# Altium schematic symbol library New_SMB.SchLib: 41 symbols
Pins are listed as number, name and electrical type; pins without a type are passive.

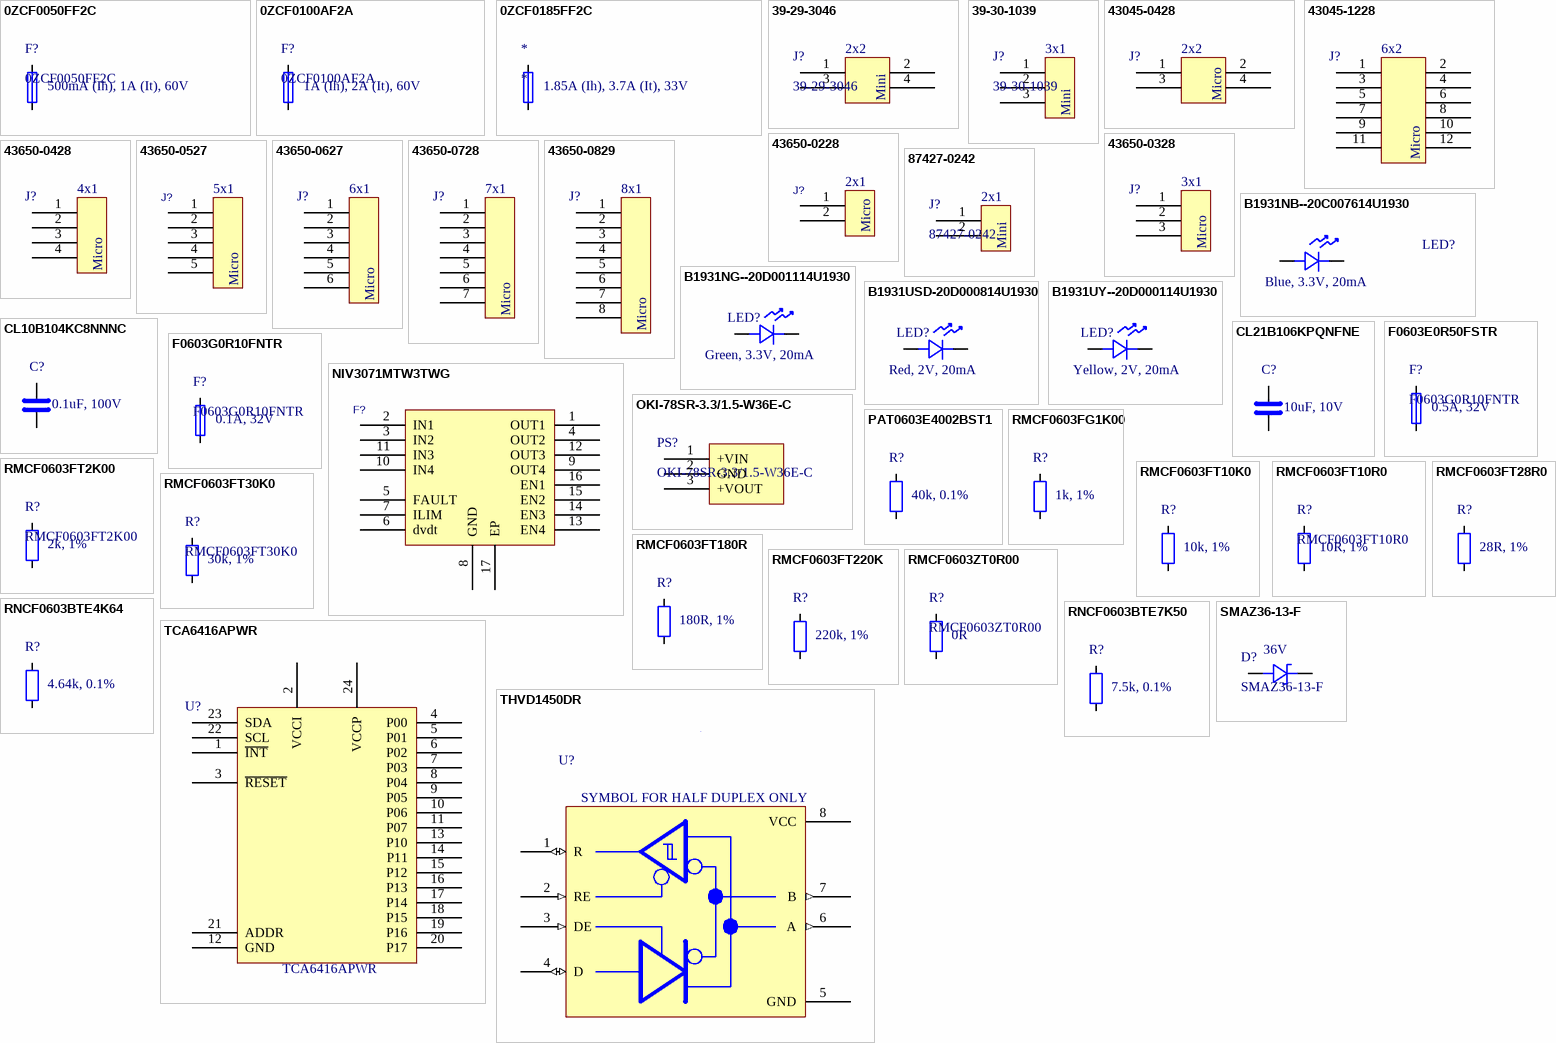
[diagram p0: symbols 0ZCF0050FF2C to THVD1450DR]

## 0ZCF0050FF2C
designator F?  Parameter 1: 500mA (Ih), 1A (It), 60V
PTC Resettable Fuse, 60V, 0.3ohm, Surface Mount; Manufacturer: Bel; Power: 1.5W; Thermistor Application: TEMPERATURE SENSING
footprint 0ZCF
pins: 1, 2

## 0ZCF0100AF2A
designator F?  Parameter 1: 1A (Ih), 2A (It), 60V
PTC Resettable Fuse, 60V, 0.09ohm, Surface Mount; Manufacturer: Bel; Thermistor Application: TEMPERATURE SENSING
footprint 0ZCF
pins: 1, 2

## 0ZCF0185FF2C
designator *  Parameter 1: 1.85A (Ih), 3.7A (It), 33V
PTC Resettable Fuse, 33V, 0.04ohm, Surface Mount; Manufacturer: Bel; Manufacturer Part Number: 0ZCF0185FF2C; Power: 1.5W; Thermistor Application: TEMPERATURE SENSING
footprint 0ZCF
pins: 1, 2

## 39-29-3046
designator J?  Parameter 1: 2x2  Parameter 2: Mini
Rectangular Power Connector, 4 Contact(s), Male, Solder Terminal, Plug; Manufacturer: Molex; Connector Type: Power,Rectangular; Option: General Purpose; Contact Resistance: 10mR; Contact Style: SQ PIN-SKT; Dielectric Withstanding Voltage (AC): 1.5kV; Durability: 30Cycles; Empty Shell: No; Insertion Force-Max: 6.672N; Insulation Resistance: 1GR; Mating Information: MULTIPLE MATING PARTS AVAILABLE; Number Of Connectors: 1; Number Of PCB Rows: 2; Polarization Key: POLARIZED HOUSING; Rated Current (Signal): 8A; Number of Contacts: 4; Withdrawl Force-Min: 3.1136N; Body Breadth: 0.378inch; Body Depth: 0.504inch; Body Length: 0.38inch; Mating Contact Pitch: 0.165inch; Mounting Option 1: POLARIZED LCK; Mounting Option 2: LOCKING; PCB Contact Row Spacing: 5.5118mm; Plating Thickness: 35uin; Reference Standard: UL; Reliability: COMMERCIAL
footprint 39-29-3046
pins: 1, 2, 3, 4

## 39-30-1039
designator J?  Parameter 1: 3x1  Parameter 2: Mini
Rectangular Power Connector, 3 Contact(s), Male, Solder Terminal, Plug; Manufacturer: Molex; Manufacturer Series: 5566; Connector Type: Power,Rectangular; Option: General Purpose; Board Mounting Option: COMPLIANT BOARDLOCK; Contact Resistance: 10mR; Contact Style: SQ PIN-SKT; Dielectric Withstanding Voltage (AC): 1.5kV; Durability: 30Cycles; Empty Shell: No; Insulation Resistance: 1GR; Mating Information: MULTIPLE MATING PARTS AVAILABLE; Rated Current (Signal): 9A; Number of Contacts: 3; Insertion Force-Max: 6.672N; Number Of Connectors: 1; Polarization Key: HOUSING SIDE; Withdrawl Force-Min: 3.1136N; Body Breadth: 0.213inch; Body Depth: 0.504inch; Body Length: 0.543inch; Mounting Option 1: POLARIZED LCK; Mounting Option 2: LOCKING; Plating Thickness: 35uin; Mating Contact Pitch: 0.165inch; Reference Standard: UL; Reliability: COMMERCIAL
footprint 39-30-1039
pins: 1, 2, 3

## 43045-0428
designator J?  Parameter 1: 2x2  Parameter 2: Micro  (hidden comment: 43045-0428)
Board Connector, 4 Contact(s), 2 Row(s), Male, Straight, Solder Terminal, Locking, Black Insulator, Receptacle; Manufacturer: Molex; Throw Configuration: S0P4; Option: General Purpose; Board Mounting Option: PEG; Contact Resistance: 10mR; Contact Style: SQ PIN-SKT; Filter Feature: No; Insertion Force-Max: 8.0064N; Insulation Resistance: 1GR; Mating Information: MULTIPLE MATING PARTS AVAILABLE; Rated Current (Signal): 2.5A; Withdrawl Force-Min: 3.5584N; Body Breadth: 0.29inch; Body Depth: 0.39inch; Body Length: 0.38inch; Plating Thickness: 15uin; Reference Standard: UL; Reliability: COMMERCIAL; Number Of Connectors: 1; Number of Rows Loaded: 2; Number of Contacts: 4
footprint 43045-0428
pins: 1, 2, 3, 4

## 43045-1228
designator J?  Parameter 1: 6x2  Parameter 2: Micro  (hidden comment: 43045-1228)
Board Connector, 12 Contact(s), 2 Row(s), Male, Straight, Solder Terminal, Locking, Black Insulator, Receptacle; Manufacturer: Molex; Throw Configuration: S0P12; Option: General Purpose; Board Mounting Option: PEG; Contact Resistance: 10mR; Contact Style: SQ PIN-SKT; Filter Feature: No; Insertion Force-Max: 8.0064N; Insulation Resistance: 1GR; Mating Information: MULTIPLE MATING PARTS AVAILABLE; Number Of Connectors: 1; Number of Rows Loaded: 2; Rated Current (Signal): 2.5A; Number of Contacts: 12; Withdrawl Force-Min: 3.5584N; Body Breadth: 0.29inch; Body Depth: 0.39inch; Body Length: 0.852inch; Plating Thickness: 15uin; Reference Standard: UL; Reliability: COMMERCIAL
footprint 43045-1228
pins: 1, 2, 3, 4, 5, 6, 7, 8, 9, 10, 11, 12

## 43650-0228
designator J?  Parameter 1: 2x1  Parameter 2: Micro  (hidden comment: 43650-0228)
Rectangular Power Connector, 2 Contact(s), Female, Solder Terminal; Manufacturer: Molex; Manufacturer Series: 43650; Connector Type: Power,Rectangular; Option: General Purpose; Board Mounting Option: PEG; Body/Shell Style: RECEPTACLE; Contact Resistance: 10mR; Contact Style: SQ PIN-SKT; Dielectric Withstanding Voltage (AC): 1.5kV; Durability: 30Cycles; Empty Shell: No; Insertion Force-Max: 8.0064N; Insulation Resistance: 1GR; Mating Information: MULTIPLE MATING PARTS AVAILABLE; Number Of Connectors: 1; Polarization Key: POLARIZED HOUSING; Rated Current (Signal): 5A; Number of Contacts: 2; Withdrawl Force-Min: 3.614N; Body Breadth: 0.219inch; Body Depth: 0.39inch; Body Length: 0.38inch; Mating Contact Pitch: 0.118inch; Mounting Option 1: POLARIZED LCK; Mounting Option 2: LOCKING; Plating Thickness: 15uin; Reference Standard: UL; Reliability: COMMERCIAL
footprint 0436500228
footprint 43650-0228
pins: 1, 2

## 43650-0328
designator J?  Parameter 1: 3x1  Parameter 2: Micro  (hidden comment: 43650-0328)
Rectangular Power Connector, 3 Contact(s), Female, Solder Terminal; Manufacturer: Molex; Manufacturer Series: 43650; Connector Type: Power,Rectangular; Option: General Purpose; Board Mounting Option: PEG; Body/Shell Style: RECEPTACLE; Contact Resistance: 10mR; Contact Style: SQ PIN-SKT; Dielectric Withstanding Voltage (AC): 1.5kV; Durability: 30Cycles; Empty Shell: No; Insertion Force-Max: 8.0064N; Insulation Resistance: 1GR; Mating Information: MULTIPLE MATING PARTS AVAILABLE; Number Of Connectors: 1; Polarization Key: POLARIZED HOUSING; Rated Current (Signal): 5A; Number of Contacts: 3; Withdrawl Force-Min: 3.614N; Body Breadth: 0.219inch; Body Depth: 0.39inch; Body Length: 0.498inch; Mating Contact Pitch: 0.118inch; Mounting Option 1: POLARIZED LCK; Mounting Option 2: LOCKING; Plating Thickness: 15uin; Reference Standard: UL; Reliability: COMMERCIAL
footprint 43650-0328
pins: 1, 2, 3

## 43650-0428
designator J?  Parameter 1: 4x1  Parameter 2: Micro  (hidden comment: 43650-0428)
Rectangular Power Connector, 4 Contact(s), Female, Solder Terminal; Manufacturer: Molex; Manufacturer Series: 43650; Connector Type: Power,Rectangular; Option: General Purpose; Board Mounting Option: PEG; Body/Shell Style: RECEPTACLE; Contact Resistance: 10mR; Contact Style: SQ PIN-SKT; Dielectric Withstanding Voltage (AC): 1.5kV; Durability: 30Cycles; Empty Shell: No; Insertion Force-Max: 8.0064N; Insulation Resistance: 1GR; Mating Information: MULTIPLE MATING PARTS AVAILABLE; Number Of Connectors: 1; Polarization Key: POLARIZED HOUSING; Rated Current (Signal): 5A; Number of Contacts: 4; Withdrawl Force-Min: 3.614N; Body Breadth: 0.219inch; Body Depth: 0.39inch; Body Length: 0.616inch; Mating Contact Pitch: 0.118inch; Mounting Option 1: POLARIZED LCK; Mounting Option 2: LOCKING; Plating Thickness: 15uin; Reference Standard: UL; Reliability: COMMERCIAL
footprint 43650-0428
pins: 1, 2, 3, 4

## 43650-0527
designator J?  Parameter 1: 5x1  Parameter 2: Micro  (hidden comment: 43650-0527)
Rectangular Power Connector, 5 Contact(s), Female, Solder Terminal; Manufacturer: Molex; Connector Type: Power,Rectangular; Option: General Purpose; Board Mounting Option: PEG; Body/Shell Style: RECEPTACLE; Contact Resistance: 10mR; Contact Style: SQ PIN-SKT; Dielectric Withstanding Voltage (AC): 1.5kV; Durability: 30Cycles; Empty Shell: No; Insertion Force-Max: 8.0064N; Insulation Resistance: 1GR; Mating Information: MULTIPLE MATING PARTS AVAILABLE; Number Of Connectors: 1; Polarization Key: POLARIZED HOUSING; Rated Current (Signal): 5A; Number of Contacts: 5; Withdrawl Force-Min: 3.614N; Body Breadth: 0.219inch; Body Depth: 0.39inch; Body Length: 0.734inch; Mating Contact Pitch: 0.118inch; Mounting Option 1: POLARIZED LCK; Mounting Option 2: LOCKING; Plating Thickness: 100uin; Reference Standard: UL; Reliability: COMMERCIAL
footprint 0436500527
footprint 43650-0527
pins: 1, 2, 3, 4, 5

## 43650-0627
designator J?  Parameter 1: 6x1  Parameter 2: Micro  (hidden comment: 43650-0627)
Rectangular Power Connector, 6 Contact(s), Female, Solder Terminal; Manufacturer: Molex; Manufacturer Series: 43650; Connector Type: Power,Rectangular; Option: General Purpose; Board Mounting Option: PEG; Body/Shell Style: RECEPTACLE; Contact Resistance: 10mR; Contact Style: SQ PIN-SKT; Dielectric Withstanding Voltage (AC): 1.5kV; Durability: 30Cycles; Empty Shell: No; Insertion Force-Max: 8.0064N; Insulation Resistance: 1GR; Mating Information: MULTIPLE MATING PARTS AVAILABLE; Number Of Connectors: 1; Polarization Key: POLARIZED HOUSING; Rated Current (Signal): 5A; Number of Contacts: 6; Withdrawl Force-Min: 3.614N; Body Breadth: 0.219inch; Body Depth: 0.39inch; Body Length: 0.852inch; Mating Contact Pitch: 0.118inch; Mounting Option 1: POLARIZED LCK; Mounting Option 2: LOCKING; Plating Thickness: 100uin; Reference Standard: UL; Reliability: COMMERCIAL
footprint 43650-0627
pins: 1, 2, 3, 4, 5, 6

## 43650-0728
designator J?  Parameter 1: 7x1  Parameter 2: Micro  (hidden comment: 43650-0728)
Rectangular Power Connector, 7 Contact(s), Female, Solder Terminal; Manufacturer: Molex; Manufacturer Series: 43650; Connector Type: Power,Rectangular; Option: General Purpose; Board Mounting Option: PEG; Body/Shell Style: RECEPTACLE; Contact Resistance: 10mR; Contact Style: SQ PIN-SKT; Dielectric Withstanding Voltage (AC): 1.5kV; Durability: 30Cycles; Empty Shell: No; Insertion Force-Max: 8.0064N; Insulation Resistance: 1GR; Mating Information: MULTIPLE MATING PARTS AVAILABLE; Number Of Connectors: 1; Polarization Key: POLARIZED HOUSING; Rated Current (Signal): 5A; Number of Contacts: 7; Withdrawl Force-Min: 3.614N; Body Breadth: 0.219inch; Body Depth: 0.39inch; Body Length: 0.97inch; Mating Contact Pitch: 0.118inch; Mounting Option 1: POLARIZED LCK; Mounting Option 2: LOCKING; Plating Thickness: 15uin; Reference Standard: UL; Reliability: COMMERCIAL
footprint 43650-0728
pins: 1, 2, 3, 4, 5, 6, 7

## 43650-0829
designator J?  Parameter 1: 8x1  Parameter 2: Micro  (hidden comment: 43650-0829)
Rectangular Power Connector, 8 Contact(s), Female, Solder Terminal; Manufacturer: Molex; Manufacturer Series: 43650; Connector Type: Power,Rectangular; Option: General Purpose; Board Mounting Option: PEG; Body/Shell Style: RECEPTACLE; Contact Resistance: 10mR; Contact Style: SQ PIN-SKT; Dielectric Withstanding Voltage (AC): 1.5kV; Durability: 30Cycles; Empty Shell: No; Insertion Force-Max: 8.0064N; Insulation Resistance: 1GR; Mating Information: MULTIPLE MATING PARTS AVAILABLE; Number Of Connectors: 1; Polarization Key: POLARIZED HOUSING; Rated Current (Signal): 5A; Number of Contacts: 8; Withdrawl Force-Min: 3.614N; Body Breadth: 0.219inch; Body Depth: 0.39inch; Body Length: 1.089inch; Mating Contact Pitch: 0.118inch; Mounting Option 1: POLARIZED LCK; Mounting Option 2: LOCKING; Plating Thickness: 30uin; Reference Standard: UL; Reliability: COMMERCIAL
footprint 43650-0829
pins: 1, 2, 3, 4, 5, 6, 7, 8

## 87427-0242
designator J?  Parameter 1: 2x1  Parameter 2: Mini
Rectangular Power Connector, 2 Contact(s), Male, Solder Terminal, Receptacle; Manufacturer: Molex; Connector Type: Power,Rectangular; Option: General Purpose; Contact Resistance: 10mR; Contact Style: SQ PIN-SKT; Dielectric Withstanding Voltage (AC): 1.5kV; Durability: 30Cycles; Empty Shell: No; Insertion Force-Max: 6.672N; Insulation Resistance: 1GR; Mating Information: MULTIPLE MATING PARTS AVAILABLE; Number Of Connectors: 1; Number Of PCB Rows: 2; Polarization Key: POLARIZED HOUSING; Rated Current (Signal): 9A; Withdrawl Force-Min: 3.0024N; Body Breadth: 0.449inch; Body Depth: 0.531inch; Body Length: 0.213inch; Mating Contact Pitch: 0.165inch; Mounting Option 1: POLARIZED LCK; Mounting Option 2: LOCKING; PCB Contact Row Spacing: 4.191mm; Plating Thickness: 100uin; Reference Standard: UL; Reliability: COMMERCIAL
footprint 87427-0242
pins: 1, 2

## B1931NB--20C007614U1930
designator LED?  Parameter 1: Blue, 3.3V, 20mA  (hidden comment: B1931NB--20C007614U1930)
Led Blue Clear 1608 SMD; Manufacturer: Inolux
footprint LED_0603
pins: 1, 2

## B1931NG--20D001114U1930
designator LED?  Parameter 1: Green, 3.3V, 20mA  (hidden comment: B1931NG--20D001114U1930)
Led Green Diffused 0603 SMD; Manufacturer: Inolux
footprint LED_0603
pins: 1, 2

## B1931USD-20D000814U1930
designator LED?  Parameter 1: Red, 2V, 20mA  (hidden comment: B1931USD-20D000814U1930)
Led Red Diffused 0603 SMD; Manufacturer: Inolux
footprint LED_0603
pins: 1, 2

## B1931UY--20D000114U1930
designator LED?  Parameter 1: Yellow, 2V, 20mA  (hidden comment: B1931UY--20D000114U1930)
Led Yellow Clear 1608 SMD; Manufacturer: Inolux
footprint LED_0603
pins: 1, 2

## CL10B104KC8NNNC
designator C?  Parameter 1: 0.1uF, 100V  (hidden comment: CL10B104KC8NNNC)
Ceramic Capacitor, Multilayer, Ceramic, 100V, 10% +Tol, 10% -Tol, X7R, 15% TC, 0.1uF, Surface Mount, 0603; Manufacturer: Samsung; Multilayer: Yes; Value: 100nF
footprint C_0603
pins: 1, 2

## CL21B106KPQNFNE
designator C?  Parameter 1: 10uF, 10V  (hidden comment: CL21B106KPQNFNE)
Ceramic Capacitor, Multilayer, Ceramic, 10V, 10% +Tol, 10% -Tol, X7R, 15% TC, 10uF, Surface Mount, 0805; Manufacturer: Samsung; Multilayer: Yes
footprint C_0805
pins: 1, 2

## F0603E0R50FSTR
designator F?, comment F0603G0R10FNTR  Parameter 1: 0.5A, 32V
Electric Fuse, Fast Blow, 0.5A, 32VAC, 32VDC, 50A (IR), Surface Mount, 0603; Manufacturer: Kyocera AVX; Manufacturer Part Number: F0603E0R50FSTR; Manufacturer Series: F0603E; Joule-integral-Nom: 0.0003J; Current Rating: 500mA; Voltage Rating (AC): 32V
footprint FUSE_0603
pins: 1, 2

## F0603G0R10FNTR
designator F?  Parameter 1: 0.1A, 32V
Electric Fuse, Fast Blow, 0.1A, 32VAC, 32VDC, Surface Mount; Manufacturer: Kyocera AVX; Joule-integral-Nom: 7E-06J; Current Rating: 100mA; Body Breadth: 0.81mm; Body Height: 0.61mm; Body Length or Diameter: 1.6mm; Reference Standard: UL
footprint FUSE_0603
pins: 1, 2

## NIV3071MTW3TWG
designator F?  (value not drawn)
Electronic fuse (eFuse) 4-channel, 8V to 60V, 10A in 5x6mm package Latch version; Manufacturer: onsemi
footprint 16-WQFN-5x6
pins: 1 OUT1, 2 IN1, 3 IN2, 4 OUT2, 5 FAULT, 6 dvdt, 7 ILIM, 8 GND, 9 OUT4, 10 IN4, 11 IN3, 12 OUT3, 13 EN4, 14 EN3, 15 EN2, 16 EN1, 17 EP

## OKI-78SR-3.3/1.5-W36E-C
designator PS?
DC-DC Regulated Power Supply Module, 1 Output, 5.15W, Hybrid; Manufacturer: Murata; Max Supply Voltage: 36V; Min Input Voltage: 7V; Nominal Supply Voltage: 12V; Load Regulation-Max: 0.4%; Channels: 1; Max Output Voltage: 3.432V; Min Output Voltage: 3.168V; Nominal Output Voltage: 3.3V; Surface Mount: No; Trim/Adjustable Output: No
footprint OKI-78SR-5&slash_1.5-W36E-C
pins: 1 +VIN (power), 2 GND (power), 3 +VOUT (power)

## PAT0603E4002BST1
designator R?  Parameter 1: 40k, 0.1%  (hidden comment: PAT0603E4002BST1)
Fixed Resistor, Thin Film, 0.15W, 40000ohm, 75V, 0.1% +/-Tol, 25ppm/Cel, Surface Mount, 0603; Manufacturer: Vishay Dale Thin Film; Power: 150mW; Rated Temperature: 70°C; Value: 40kR; Temperature Coefficient (ppm/Cel): 25; Reference Standard: AEC-Q200
footprint R_0603
pins: 1, 2

## RMCF0603FG1K00
designator R?  Parameter 1: 1k, 1%  (hidden comment: RMCF0603FG1K00)
Fixed Resistor, Metal Glaze/thick Film, 0.1W, 1000ohm, 75V, 1% +/-Tol, 100ppm/Cel, Surface Mount, 0603; Manufacturer: Stackpole Electronics; Power: 100mW; Rated Temperature: 70°C; Temperature Coefficient (ppm/Cel): 100; Package Height: 0.45mm; Package Length: 1.55mm; Package Width: 0.8mm; Reference Standard: AEC-Q200; Value: 1k
footprint R_0603
pins: 1, 2

## RMCF0603FT2K00
designator R?  Parameter 1: 2k, 1%
Fixed Resistor, Metal Glaze/thick Film, 0.1W, 2000ohm, 75V, 1% +/-Tol, 100ppm/Cel, Surface Mount, 0603; Manufacturer: Stackpole Electronics; Power: 100mW; Rated Temperature: 70°C; Value: 2kR; Temperature Coefficient (ppm/Cel): 100; Package Height: 0.45mm; Package Length: 1.55mm; Package Width: 0.8mm; Reference Standard: AEC-Q200
footprint C_0603
pins: 1, 2

## RMCF0603FT10K0
designator R?  Parameter 1: 10k, 1%  (hidden comment: RMCF0603FT10K0)
Fixed Resistor, Metal Glaze/thick Film, 0.1W, 10000ohm, 75V, 1% +/-Tol, 100ppm/Cel, Surface Mount, 0603; Manufacturer: Stackpole Electronics; Power: 100mW; Rated Temperature: 70°C; Temperature Coefficient (ppm/Cel): 100; Package Height: 0.45mm; Package Length: 1.55mm; Package Width: 0.8mm; Reference Standard: AEC-Q200; Value: 10k
footprint R_0603
pins: 1, 2

## RMCF0603FT10R0
designator R?  Parameter 1: 10R, 1%
Fixed Resistor, Metal Glaze/thick Film, 0.1W, 10ohm, 75V, 1% +/-Tol, 100ppm/Cel, Surface Mount, 0603; Manufacturer: Stackpole Electronics; Power: 100mW; Rated Temperature: 70°C; Value: 10R; Temperature Coefficient (ppm/Cel): 100; Package Height: 0.45mm; Package Length: 1.55mm; Package Width: 0.8mm; Reference Standard: AEC-Q200
footprint R_0603
pins: 1, 2

## RMCF0603FT28R0
designator R?  Parameter 1: 28R, 1%  (hidden comment: RMCF0603FT28R0)
Fixed Resistor, Metal Glaze/thick Film, 0.1W, 28ohm, 75V, 1% +/-Tol, 100ppm/Cel, Surface Mount, 0603; Manufacturer: Stackpole Electronics; Power: 100mW; Rated Temperature: 70°C; Temperature Coefficient (ppm/Cel): 100; Package Height: 0.45mm; Package Length: 1.55mm; Package Width: 0.8mm; Reference Standard: AEC-Q200; Value: 28
footprint R_0603
pins: 1, 2

## RMCF0603FT30K0
designator R?  Parameter 1: 30k, 1%
Fixed Resistor, Metal Glaze/thick Film, 0.1W, 30000ohm, 75V, 1% +/-Tol, 100ppm/Cel, Surface Mount, 0603; Manufacturer: Stackpole Electronics; Power: 100mW; Rated Temperature: 70°C; Value: 30kR; Temperature Coefficient (ppm/Cel): 100; Package Height: 0.45mm; Package Length: 1.55mm; Package Width: 0.8mm; Reference Standard: AEC-Q200
footprint R_0603
pins: 1, 2

## RMCF0603FT180R
designator R?  Parameter 1: 180R, 1%  (hidden comment: RMCF0603FT180R)
Fixed Resistor, Metal Glaze/thick Film, 0.1W, 180ohm, 75V, 1% +/-Tol, 100ppm/Cel, Surface Mount, 0603; Manufacturer: Stackpole Electronics; Power: 100mW; Rated Temperature: 70°C; Temperature Coefficient (ppm/Cel): 100; Package Height: 0.45mm; Package Length: 1.55mm; Package Width: 0.8mm; Reference Standard: AEC-Q200; Value: 180
footprint R_0603
pins: 1, 2

## RMCF0603FT220K
designator R?  Parameter 1: 220k, 1%  (hidden comment: RMCF0603FT220K)
Fixed Resistor, Metal Glaze/thick Film, 0.1W, 220000ohm, 75V, 1% +/-Tol, 100ppm/Cel, Surface Mount, 0603; Manufacturer: Stackpole Electronics; Power: 100mW; Rated Temperature: 70°C; Temperature Coefficient (ppm/Cel): 100; Package Height: 0.45mm; Package Length: 1.55mm; Package Width: 0.8mm; Reference Standard: AEC-Q200; Value: 220k
footprint R_0603
pins: 1, 2

## RMCF0603ZT0R00
designator R?  Parameter 1: 0R
Fixed Resistor, Metal Glaze/thick Film, 0.1W, 0ohm, Surface Mount, 0603; Manufacturer: Stackpole Electronics; Power: 100mW; Rated Temperature: 70°C; Working Voltage: 75V; Package Height: 0.45mm; Package Length: 1.55mm; Package Width: 0.8mm; Reference Standard: AEC-Q200; Value: 0R
footprint R_0603
pins: 1, 2

## RNCF0603BTE4K64
designator R?  Parameter 1: 4.64k, 0.1%  (hidden comment: RNCF0603BTE4K64)
Fixed Resistor, Thin Film, 0.166W, 4640ohm, 100V, 0.1% +/-Tol, 25ppm/Cel, Surface Mount, 0603; Manufacturer: Stackpole Electronics; Additional Feature: PRECISION; Power: 166mW; Rated Temperature: 70°C; Temperature Coefficient (ppm/Cel): 25; Package Height: 0.45mm; Package Length: 1.55mm; Package Width: 0.8mm; Reference Standard: AEC-Q200; Value: 4.64k
footprint R_0603
pins: 1, 2

## RNCF0603BTE7K50
designator R?  Parameter 1: 7.5k, 0.1%  (hidden comment: RNCF0603BTE7K50)
Fixed Resistor, Thin Film, 0.166W, 7500ohm, 100V, 0.1% +/-Tol, 25ppm/Cel, Surface Mount, 0603; Manufacturer: Stackpole Electronics; Additional Feature: PRECISION; Power: 166mW; Rated Temperature: 70°C; Temperature Coefficient (ppm/Cel): 25; Package Height: 0.45mm; Package Length: 1.55mm; Package Width: 0.8mm; Reference Standard: AEC-Q200; Value: 7.5k
footprint R_0603
pins: 1, 2

## SMAZ36-13-F
designator D?  Parameter 1: 36V
Zener Diode, 36V V(Z), 5%, 1W, Silicon, Unidirectional; Manufacturer: Diodes; Package Body Material: Plastic; Dynamic Impedance-Max: 40R; Number of Elements: 1; Time @ Peak Reflow Temperature-Max (s): 40s; Test Current: 10mA; Qualification Status: Not Qualified
footprint SMAZ36-13-F
pins: 1, 2

## TCA6416APWR
designator U?
Parallel I/O Port, 16-Bit, 16 I/O, CMOS, PDSO24; Manufacturer: Texas Instruments; Package Body Material: Plastic; Power Supplies: 1.8/5V; Max Supply Voltage: 5.5V; Min Supply Voltage: 1.65V; Nominal Supply Voltage: 1.8V; Number of Bits: 16; Number of Ports: 2; Package Equivalence Code: TSSOP24,.25; Qualification Status: Not Qualified
footprint TSSOP24
pins: 1 ~{INT}, 2 VCCI, 3 ~{RESET}, 4 P00, 5 P01, 6 P02, 7 P03, 8 P04, 9 P05, 10 P06, 11 P07, 12 GND, 13 P10, 14 P11, 15 P12, 16 P13, 17 P14, 18 P15, 19 P16, 20 P17, 21 ADDR, 22 SCL, 23 SDA, 24 VCCP

## THVD1450DR
designator U?  (value not drawn)
Line Transceiver, 1 Func, 1 Driver, 1 Rcvr, PDSO8; Manufacturer: Texas Instruments; Package Body Material: Plastic; Differential Output: Yes; Driver Number of Bits: 1; Input Characteristics: DIFFERENTIAL SCHMITT TRIGGER; Receive Delay-Max: 40ns; Max Supply Voltage: 5.5V; Min Supply Voltage: 3V; Nominal Supply Voltage: 5V; Transmit Delay-Max: 20ns
footprint 8-SOIC
pins: 1 R (io), 2 RE (in), 3 DE (in), 4 D (io), 5 GND, 6 A (out), 7 B (out), 8 VCC

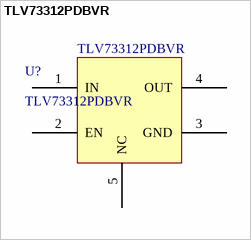
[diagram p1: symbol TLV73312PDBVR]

## TLV73312PDBVR
designator U?
Fixed Positive LDO Regulator, 1.2V, 0.45V Dropout, PDSO5; Manufacturer: Texas Instruments; Package Body Material: Plastic; Dropout Voltage1-Max: 450mV; Max Supply Voltage: 5.5V; Min Input Voltage: 1.4V; Channels: 1; Output Current1-Max: 300mA; Output Voltage1-Max: 1.2168V; Output Voltage1-Min: 1.1832V; Regulator Type: FIXED POSITIVE SINGLE OUTPUT LDO REGULATOR
footprint SOP6
pins: 1 IN, 2 EN, 3 GND, 4 OUT, 5 NC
